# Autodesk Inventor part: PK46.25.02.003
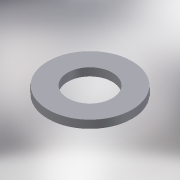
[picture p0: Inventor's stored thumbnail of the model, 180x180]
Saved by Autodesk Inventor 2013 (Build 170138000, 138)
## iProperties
Created: 2005-04
Part Number: PK46.25.02.003
Material: Steel, Mild
Document SubType Name: Modeling
Designer: salex
Manufacturer: Standard
Standards Organization: Custom
Density: 7.86 g/cm^3
Mass: 2054.45 g
Surface Area: 457.416 cm^2
Volume: 261.381 cm^3
Author: salex
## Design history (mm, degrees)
sketch "Эскиз1"
  geometry: C1 r 45 at (0, 0); C2 r 85 at (0, 0)
  constraints: 2 centre point, 1 coincident
  dimensions: "d0" = 170 diameter of C2; "d1" = 90 diameter of C1
extrude "Выдавливание1" new body sketch "Эскиз1" distance "d2" = 16; taper "d3" = 0 deg
body "Solid1"
